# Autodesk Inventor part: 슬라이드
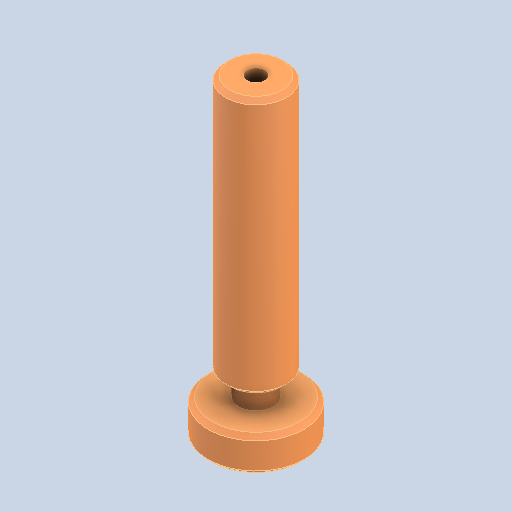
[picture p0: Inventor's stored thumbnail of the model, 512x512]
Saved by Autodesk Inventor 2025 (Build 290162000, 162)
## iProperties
Created: 2025-08
Part Number: 슬라이드
Material: 강철, 연강
Document SubType Name: Modeling
Designer: infra02
Density: 7.86 g/cm^3
Appearance: 기본값
Author: jhkim
Sending System: Autodesk Inventor 2026
Preprocessor: ST-DEVELOPER v20.1
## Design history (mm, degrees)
feature "솔리드1"
node "솔리드2"
